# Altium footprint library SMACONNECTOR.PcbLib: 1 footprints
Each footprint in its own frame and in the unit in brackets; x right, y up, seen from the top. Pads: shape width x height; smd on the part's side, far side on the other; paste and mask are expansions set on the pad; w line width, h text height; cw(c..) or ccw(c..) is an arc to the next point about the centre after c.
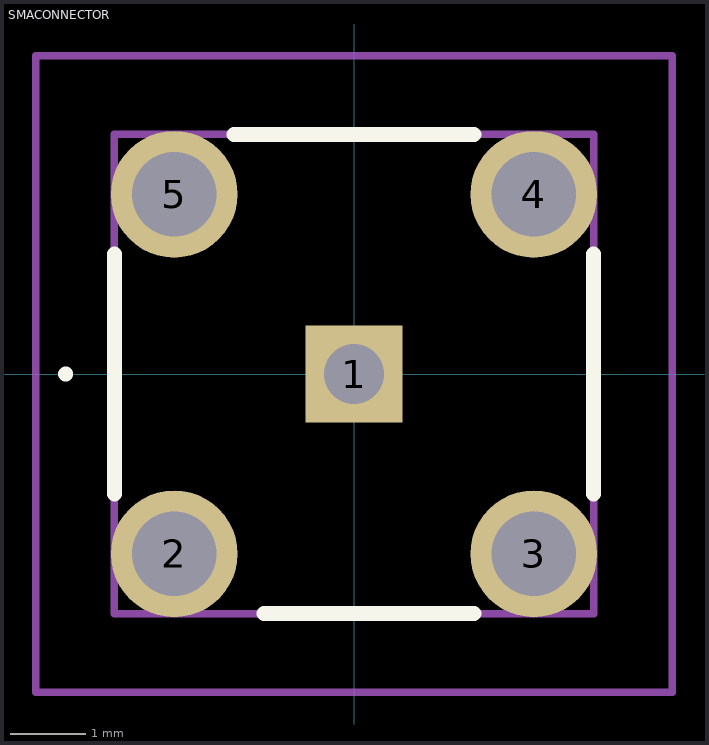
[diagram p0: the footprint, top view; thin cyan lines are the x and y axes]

## SMACONNECTOR [mm]
pads (5):
  rect 1.3x1.3 hole 0.8: 1(0,0)
  round 1.695 hole 1.13: 2(-2.4,-2.4) 3(2.4,-2.4) 4(2.4,2.4) 5(-2.4,2.4)
Top Overlay:
  lines w0.1: -3.9,0 cw(c-3.85,0) -3.8,0 ; -3.9,0 -3.9,0 ; -3.9,0 ccw(c-3.85,0) -3.8,0 ; -3.8,0 -3.8,0
  lines w0.2: -3.2,-1.6 -3.2,1.6 ; -1.6,3.2 1.6,3.2 ; -1.2,-3.2 1.6,-3.2 ; 3.2,-1.6 3.2,1.6
Mechanical 15:
  lines w0.1: -3.2,-3.2 3.2,-3.2 3.2,3.2 -3.2,3.2 -3.2,-3.2
Mechanical 20:
  lines w0.1: -4.248,-4.247 4.248,-4.247 4.248,4.248 -4.248,4.248 -4.248,-4.247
